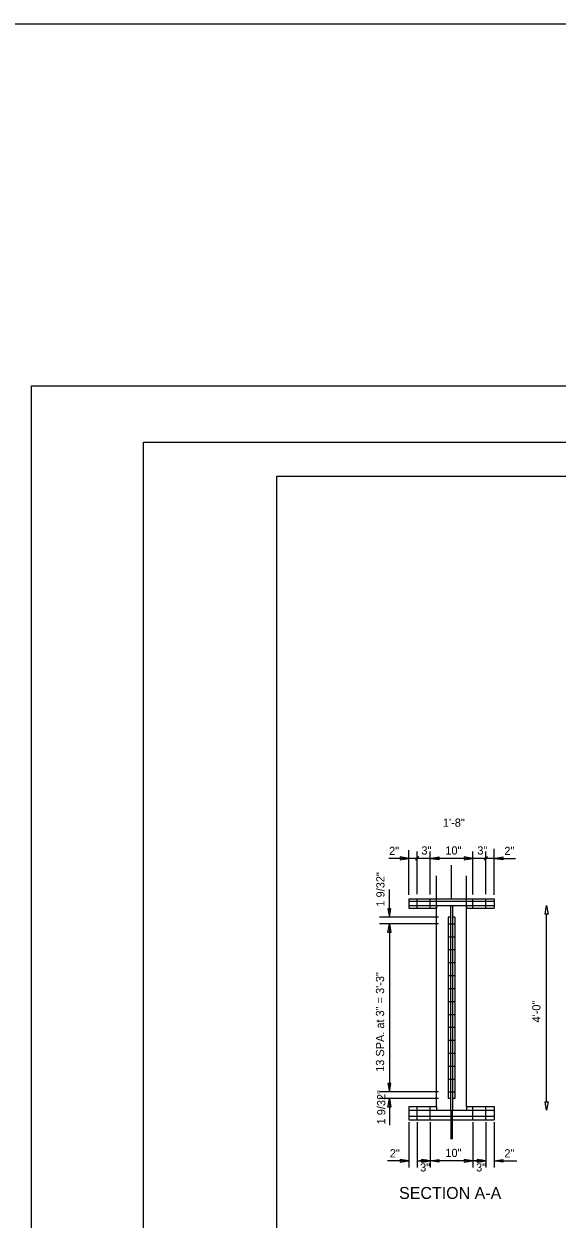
# Model space of a CAD drawing. Extents: x 4944 to 17449, y 3824 to 49087.
# Drawn here: x 12334 to 13083, y 33442 to 35123 of the extents above; entities that cross this region are included whole.
import ezdxf

# ---------------------------------------------------------------- set-up
doc = ezdxf.new("R2010")
doc.units = 0
for name, color, linetype in [('1', 7, 'Continuous'), ('36_S_LINES', 7, 'Continuous'), ('37_S_TXT', 7, 'Continuous'), ('3A', 7, 'Continuous'), ('BEAM', 7, 'Continuous'), ('DIM', 7, 'Continuous'), ('HATCH', 7, 'Continuous'), ('Level 14', 7, 'Continuous'), ('Level 25', 7, 'Continuous')]:
    doc.layers.add(name, color=color, linetype=linetype)

msp = doc.modelspace()

# ---------------------------------------------------------------- linework, layer by layer
at = {"layer": '1'}
for points in [[(12886.7, 33879.3), (12886.7, 33892.4)], [(12904.9, 33879.3), (12904.9, 33892.4)], [(12964.9, 33879.3), (12964.9, 33892.4)], [(12983.1, 33879.3), (12983.1, 33892.4)], [(12930.4, 33857.3), (12939.5, 33857.3)], [(12930.4, 33839.1), (12939.5, 33839.1)], [(12930.4, 33820.9), (12939.5, 33820.9)], [(12930.4, 33802.7), (12939.5, 33802.7)], [(12930.4, 33784.5), (12939.5, 33784.5)], [(12930.4, 33766.3), (12939.5, 33766.3)], [(12930.4, 33748.1), (12939.5, 33748.1)], [(12930.4, 33729.9), (12939.5, 33729.9)], [(12930.4, 33711.7), (12939.5, 33711.7)], [(12930.4, 33693.5), (12939.5, 33693.5)], [(12930.4, 33675.3), (12939.5, 33675.3)], [(12930.4, 33657.2), (12939.5, 33657.2)], [(12930.4, 33639), (12939.5, 33639)], [(12930.4, 33620.8), (12939.5, 33620.8)], [(12886.7, 33581.5), (12886.7, 33600.6)], [(12904.9, 33581.5), (12904.9, 33600.6)], [(12964.9, 33581.5), (12964.9, 33600.6)], [(12983.1, 33581.5), (12983.1, 33600.6)]]:
    msp.add_lwpolyline(points, dxfattribs=at)
at = {"layer": '36_S_LINES'}
for p, q in [((12874.9, 33949.2), (12846.8, 33949.2)), ((12874.9, 33898), (12874.9, 33961)), ((12904.9, 33949.2), (12874.9, 33949.2)), ((12889.2, 33951.7), (12884.2, 33946.7)), ((12964.9, 33949.2), (12904.9, 33949.2)), ((12994.9, 33949.2), (12964.9, 33949.2)), ((12985.6, 33951.7), (12980.6, 33946.7)), ((12994.9, 33898), (12994.9, 33962.7)), ((12994.9, 33949.2), (13024.7, 33949.2)), ((12847.7, 33866.4), (12847.7, 33905.7)), ((12916.9, 33866.4), (12833.7, 33866.4)), ((12847.7, 33857.3), (12847.7, 33620.8)), ((12916.9, 33611.7), (12833.7, 33611.7)), ((12847.7, 33611.7), (12847.7, 33574.2)), ((12874.9, 33578.5), (12874.9, 33514.4)), ((12994.9, 33578.5), (12994.9, 33514.4)), ((12874.9, 33524), (12845.1, 33524)), ((12886.7, 33524), (12904.9, 33524)), ((12964.9, 33524), (12904.9, 33524)), ((12983.1, 33524), (12964.9, 33524)), ((12994.9, 33524), (13026.5, 33524))]:
    msp.add_line(p, q, dxfattribs=at)
for points in [[(12862.8, 33951.2), (12862.8, 33947.2), (12874.9, 33949.2)], [(12866.9, 33948.2), (12866.9, 33950.2), (12874.9, 33949.2)], [(12866.9, 33950.2), (12866.9, 33948.2), (12874.9, 33949.2)], [(12917, 33951.2), (12917, 33947.2), (12904.9, 33949.2)], [(12912.9, 33948.2), (12912.9, 33950.2), (12904.9, 33949.2)], [(12912.9, 33950.2), (12912.9, 33948.2), (12904.9, 33949.2)], [(12952.8, 33951.2), (12952.8, 33947.2), (12964.9, 33949.2)], [(12956.9, 33948.2), (12956.9, 33950.2), (12964.9, 33949.2)], [(12956.9, 33950.2), (12956.9, 33948.2), (12964.9, 33949.2)], [(13007, 33951.2), (13007, 33947.2), (12994.9, 33949.2)], [(13002.9, 33948.2), (13002.9, 33950.2), (12994.9, 33949.2)], [(13002.9, 33950.2), (13002.9, 33948.2), (12994.9, 33949.2)], [(12849.7, 33878.5), (12845.7, 33878.5), (12847.7, 33866.4)], [(12849.7, 33845.1), (12845.7, 33845.1), (12847.7, 33857.3)], [(12849.7, 33632.9), (12845.7, 33632.9), (12847.7, 33620.8)], [(12849.7, 33599.5), (12845.7, 33599.5), (12847.7, 33611.7)], [(12862.8, 33526), (12862.8, 33522), (12874.9, 33524)], [(12866.9, 33525), (12866.9, 33523), (12874.9, 33524)], [(12898.8, 33526), (12898.8, 33522), (12886.7, 33524)], [(12894.7, 33525), (12894.7, 33523), (12886.7, 33524)], [(12892.8, 33526), (12892.8, 33522), (12904.9, 33524)], [(12896.9, 33525), (12896.9, 33523), (12904.9, 33524)], [(12917, 33526), (12917, 33522), (12904.9, 33524)], [(12912.9, 33525), (12912.9, 33523), (12904.9, 33524)], [(12952.8, 33526), (12952.8, 33522), (12964.9, 33524)], [(12956.9, 33525), (12956.9, 33523), (12964.9, 33524)], [(12977, 33526), (12977, 33522), (12964.9, 33524)], [(12972.9, 33525), (12972.9, 33523), (12964.9, 33524)], [(12971, 33526), (12971, 33522), (12983.1, 33524)], [(12975.1, 33525), (12975.1, 33523), (12983.1, 33524)], [(13007, 33526), (13007, 33522), (12994.9, 33524)], [(13002.9, 33525), (13002.9, 33523), (12994.9, 33524)]]:
    msp.add_lwpolyline(points, close=True, dxfattribs=at)
at = {"layer": '37_S_TXT'}
msp.add_lwpolyline([(12345.1, 34613.8), (15801.2, 34613.8), (15801.2, 32309.8), (12345.1, 32309.8)], close=True, dxfattribs=at)
at = {"layer": '3A'}
for p, q in [((12886.7, 33899), (12886.7, 33958.8)), ((12904.9, 33898.3), (12904.9, 33958.8)), ((12964.9, 33898.3), (12964.9, 33958.8)), ((12983.1, 33899), (12983.1, 33958.8)), ((12916.9, 33857.3), (12833.7, 33857.3)), ((12916.9, 33620.8), (12833.7, 33620.8)), ((12886.7, 33578.5), (12886.7, 33514.4)), ((12904.9, 33578.5), (12904.9, 33514.4)), ((12964.9, 33578.5), (12964.9, 33514.4)), ((12983.1, 33578.5), (12983.1, 33514.4))]:
    msp.add_line(p, q, dxfattribs=at)
at = {"layer": 'DEFPOINTS'}
for p, q in [((12934.9, 33892.4), (12934.9, 33939.7)), ((12914, 33600.6), (12914, 33924.8)), ((12955.8, 33600.6), (12955.8, 33924.8)), ((13068.6, 33607), (13068.6, 33871)), ((12934, 33595), (12934, 33554.6)), ((12935.9, 33595), (12935.9, 33554.6)), ((12934.9, 33581.5), (12934.9, 33554.6))]:
    msp.add_line(p, q, dxfattribs=at)
for points in [[(13066.6, 33871), (13068.6, 33883), (13070.6, 33871)], [(13070.6, 33607), (13068.6, 33595), (13066.6, 33607)]]:
    msp.add_lwpolyline(points, close=True, dxfattribs=at)
at = {"layer": 'DIM'}
msp.add_lwpolyline([(12502.3, 34534.6), (15766.4, 34534.6), (15766.4, 32422.6), (12502.3, 32422.6)], close=True, dxfattribs=at)
at = {"layer": 'HATCH'}
msp.add_line((5851.1, 35122.6), (16384.1, 35122.6), dxfattribs=at)
at = {"layer": 'Level 14'}
msp.add_lwpolyline([(15713.6, 32470.6), (12689.5, 32470.6), (12689.5, 34486.6), (15713.6, 34486.6)], close=True, dxfattribs=at)
at = {"layer": 'Level 25'}
for p, q in [((12874.9, 33892.4), (12994.9, 33892.4)), ((12874.9, 33892.4), (12874.9, 33879.3)), ((12874.9, 33889), (12994.9, 33889)), ((12874.9, 33883), (12994.9, 33883)), ((12874.9, 33879.3), (12914, 33879.3)), ((12914, 33883), (12914, 33879.3)), ((12933.4, 33883), (12933.4, 33595)), ((12936.4, 33883), (12936.4, 33595)), ((12955.8, 33883), (12955.8, 33879.3)), ((12955.8, 33879.3), (12994.9, 33879.3)), ((12994.9, 33892.4), (12994.9, 33879.3)), ((12930.4, 33866.4), (12930.4, 33611.7)), ((12933.4, 33866.4), (12930.4, 33866.4)), ((12939.5, 33866.4), (12936.4, 33866.4)), ((12939.5, 33866.4), (12939.5, 33611.7)), ((12933.4, 33611.7), (12930.4, 33611.7)), ((12939.5, 33611.7), (12936.4, 33611.7)), ((12874.9, 33600.6), (12914, 33600.6)), ((12874.9, 33600.6), (12874.9, 33581.5)), ((12874.9, 33595), (12994.9, 33595)), ((12914, 33600.6), (12914, 33595)), ((12955.8, 33600.6), (12994.9, 33600.6)), ((12955.8, 33600.6), (12955.8, 33595)), ((12994.9, 33600.6), (12994.9, 33581.5)), ((12874.9, 33586.8), (12994.9, 33586.8)), ((12874.9, 33581.5), (12994.9, 33581.5))]:
    msp.add_line(p, q, dxfattribs=at)

# ---------------------------------------------------------------- texts
at = {"layer": '3A'}
for s, p in [('2"', (12847.3, 33954)), ('3"', (12892.7, 33954.6)), ('10"', (12926.3, 33954.6)), ('3"', (12971.2, 33954.6)), ('2"', (13009.2, 33954)), ('2"', (12848.3, 33528.8)), ('10"', (12926.3, 33529.4)), ('2"', (13009.2, 33528.8)), ('3"', (12890.9, 33509)), ('3"', (12969.5, 33509))]:
    msp.add_text(s, height=11.52, dxfattribs=at).set_placement(p)
for s, p in [('1 9/32"', (12840.8, 33881.5)), ('13 SPA. at 3" = 3\'-3"', (12840.3, 33649.1)), ('1 9/32"', (12842, 33575.2))]:
    msp.add_text(s, height=11.52, rotation=90, dxfattribs=at).set_placement(p)
at = {"layer": 'BEAM'}
msp.add_text('SECTION A-A', height=16.8, dxfattribs=at).set_placement((12861.3, 33470.4))
at = {"layer": 'DEFPOINTS'}
msp.add_text('1\'-8"', height=11.52, dxfattribs=at).set_placement((12922.9, 33993.7))
msp.add_text('4\'-0"', height=11.52, rotation=90, dxfattribs=at).set_placement((13059.9, 33718.5))

doc.saveas('drawing.dxf')
